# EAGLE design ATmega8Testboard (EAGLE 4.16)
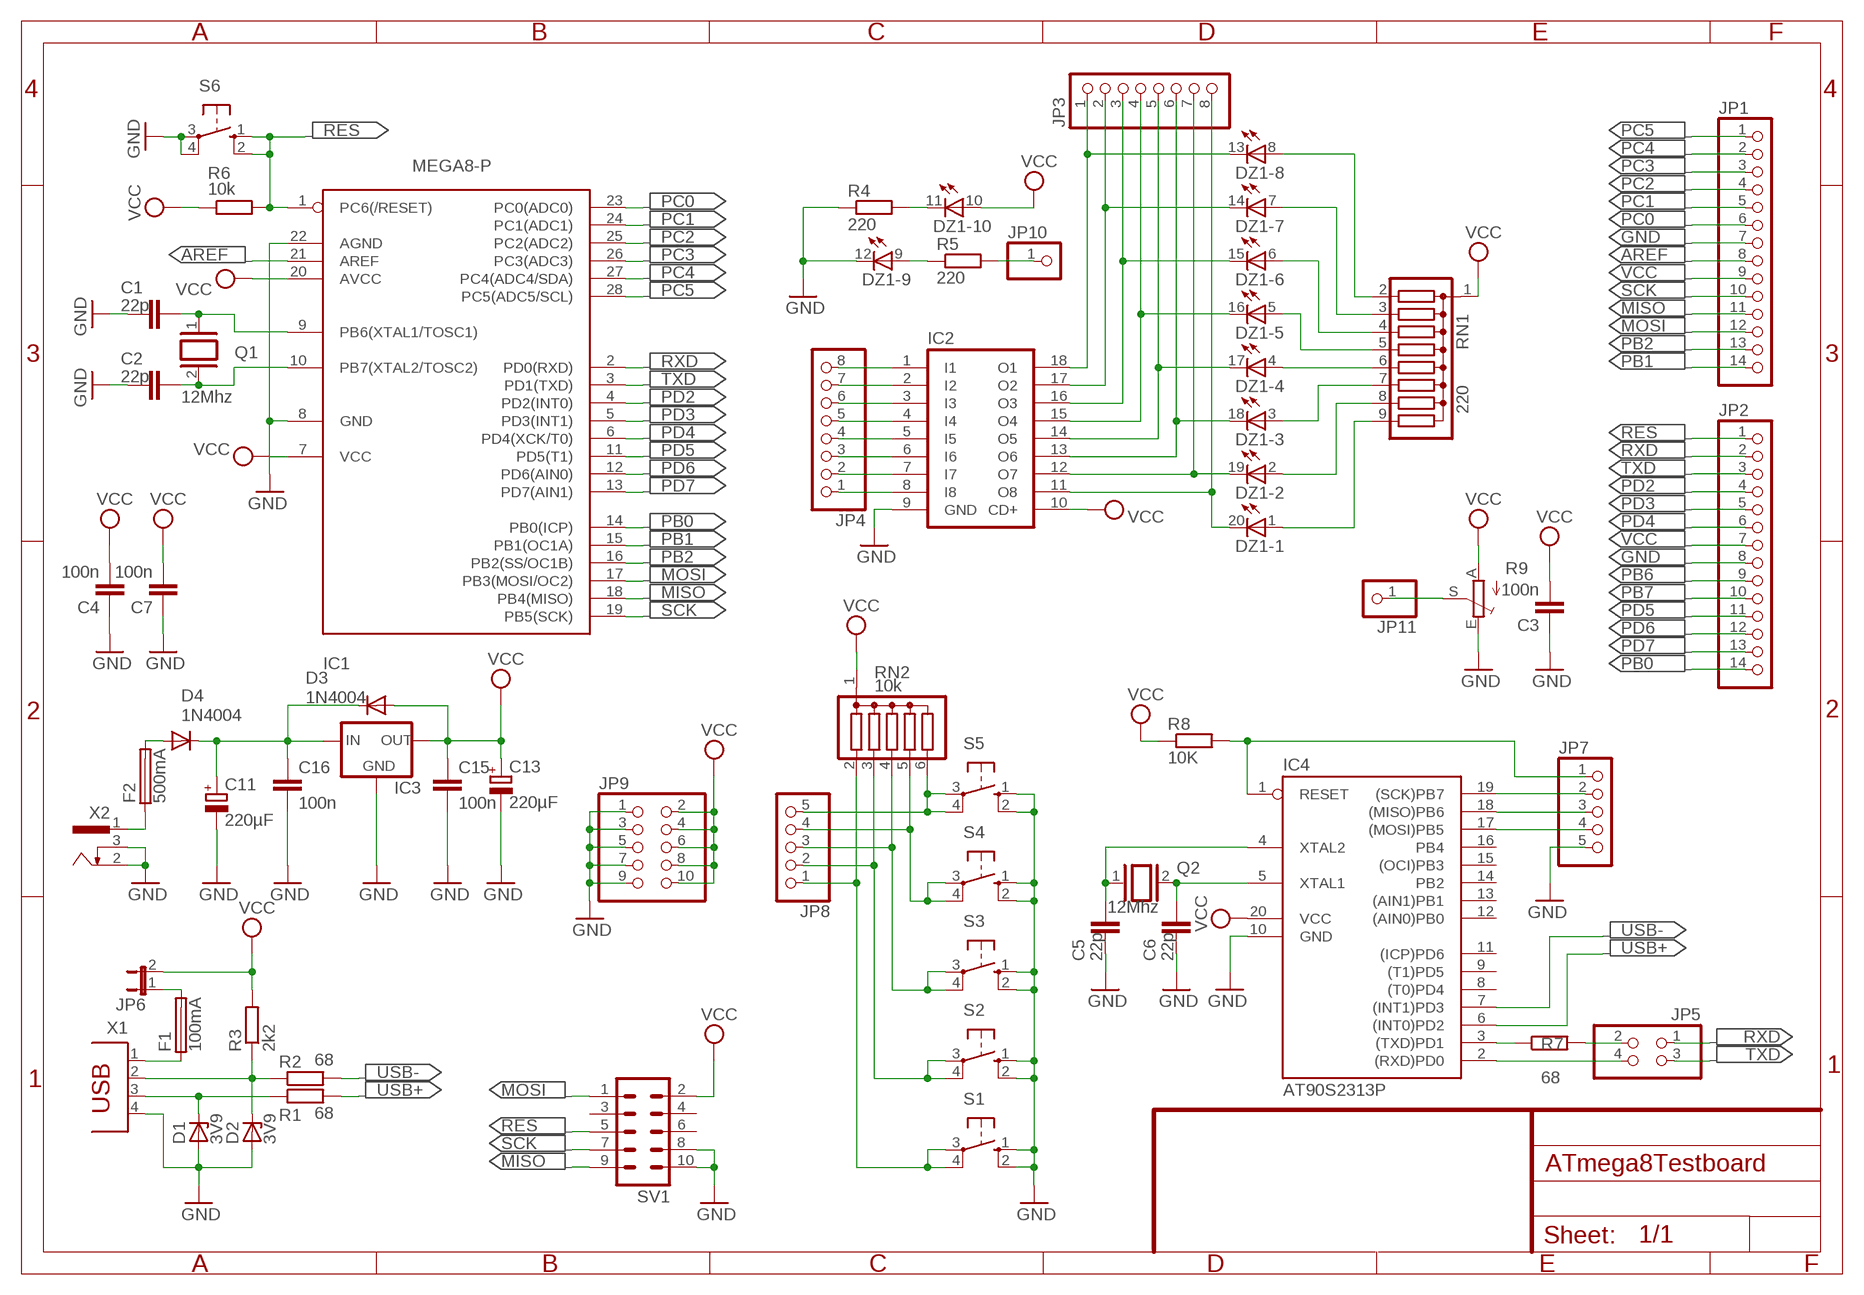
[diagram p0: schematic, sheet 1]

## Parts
C1  22p  C-EU025-024X044  [C025-024X044]
C2  22p  C-EU025-024X044  [C025-024X044]
C3  100n  C-EU025-024X044  [C025-024X044]
C4  100n  C-EU025-024X044  [C025-024X044]
C5  22p  C-EU025-024X044  [C025-024X044]
C6  22p  C-EU025-024X044  [C025-024X044]
C7  100n  C-EU025-024X044  [C025-024X044]
C11  220µF  CPOL-EUE3.5-8  [E3,5-8]
C13  220µF  CPOL-EUE3.5-8  [E3,5-8]
C15  100n  C-EU050-024X044  [C050-024X044]
C16  100n  C-EU050-024X044  [C050-024X044]
D1  3V9  BZX55  [DO35Z10]
D2  3V9  BZX55  [DO35Z10]
D3  1N4004  [DO41-10]
D4  1N4004  [DO41-10]
DZ1  LB10  [LB10]
F1  100mA  PICOFUSE  [PICOFUSE]
F2  500mA  PICOFUSE  [PICOFUSE]
IC1  MEGA8-P  [DIL28-3]
IC2  ULN2803A  [DIL18]
IC3  78XXL  [78XXL]
IC4  AT90S2313P  [DIL20]
JP1  PINHD-1X14  [1X14]
JP2  PINHD-1X14  [1X14]
JP3  PINHD-1X8  [1X08]
JP4  PINHD-1X8  [1X08]
JP5  PINHD-2X2  [2X02]
JP6  JP1E  [JP1]
JP7  PINHD-1X5  [1X05]
JP8  PINHD-1X5  [1X05]
JP9  PINHD-2X5  [2X05]
JP10  PINHD-1X1  [1X01]
JP11  PINHD-1X1  [1X01]
Q1  12Mhz  XTAL/S  [QS]
Q2  12Mhz  XTAL/S  [QS]
R1  68  R-EU_0207/10  [0207/10]
R2  68  R-EU_0207/10  [0207/10]
R3  2k2  R-EU_0207/10  [0207/10]
R4  220  R-EU_0207/10  [0207/10]
R5  220  R-EU_0207/10  [0207/10]
R6  10k  R-EU_0207/10  [0207/10]
R7  68  R-EU_0207/10  [0207/10]
R8  10K  R-EU_0207/10  [0207/10]
R9  TRIM_EU-LI15  [LI15]
RN1  220  G08R  [SIL9]
RN2  10k  G05R  [SIL6]
S1  10-XX  [B3F-10XX]
S2  10-XX  [B3F-10XX]
S3  10-XX  [B3F-10XX]
S4  10-XX  [B3F-10XX]
S5  10-XX  [B3F-10XX]
S6  10-XX  [B3F-10XX]
SV1  ML10  [ML10]
X1  PN61729  [PN61729]
X2  SCD-014A  [SCD-014-A]

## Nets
/RXD: JP5.2 R7.2
/TXD: IC4.2((RXD)PD0) JP5.4
AREF: IC1.21(AREF) JP1.8
GND: C1.1 C2.1 C3.1 C4.1 C5.1 C6.1 C7.1 C11.- C13.- C15.2 C16.2 D1.A D2.A DZ1.12(-9:C) IC1.8(GND) IC1.22(AGND) IC2.9(GND) IC3.GND IC4.10(GND) JP1.7 JP2.8 JP7.5 JP9.1 JP9.3 JP9.5 JP9.7 JP9.9 R4.1 R9.E S1.1(S) S1.2(S1) S2.1(S) S2.2(S1) S3.1(S) S3.2(S1) S4.1(S) S4.2(S1) S5.1(S) S5.2(S1) S6.3(P) S6.4(P1) SV1.8 SV1.10 X1.4 X2.2 X2.3
MISO: IC1.18(PB4(MISO)) JP1.11 SV1.9
MOSI: IC1.17(PB3(MOSI/OC2)) JP1.12 SV1.1
N$1: JP11.1 R9.S
N$3: DZ1.1(-1:A) RN1.9
N$4: DZ1.13(-8:C) IC2.18(O1) JP3.1
N$5: D1.C R1.1 X1.3
N$6: D2.C R2.1 R3.1 X1.2
N$7: DZ1.14(-7:C) IC2.17(O2) JP3.2
N$8: DZ1.15(-6:C) IC2.16(O3) JP3.3
N$9: DZ1.16(-5:C) IC2.15(O4) JP3.4
N$10: DZ1.17(-4:C) IC2.14(O5) JP3.5
N$11: DZ1.18(-3:C) IC2.13(O6) JP3.6
N$12: DZ1.19(-2:C) IC2.12(O7) JP3.7
N$13: DZ1.20(-1:C) IC2.11(O8) JP3.8
N$18: DZ1.5(-5:A) RN1.5
N$19: DZ1.4(-4:A) RN1.6
N$20: DZ1.3(-3:A) RN1.7
N$21: DZ1.2(-2:A) RN1.8
N$22: DZ1.6(-6:A) RN1.4
N$23: DZ1.7(-7:A) RN1.3
N$24: DZ1.8(-8:A) RN1.2
N$25: IC2.1(I1) JP4.8
N$26: IC2.2(I2) JP4.7
N$27: IC2.3(I3) JP4.6
N$28: IC2.4(I4) JP4.5
N$29: IC2.5(I5) JP4.4
N$30: IC2.6(I6) JP4.3
N$31: IC2.7(I7) JP4.2
N$32: IC2.8(I8) JP4.1
N$33: DZ1.11(-10:C) R4.2
N$34: DZ1.9(-9:A) R5.1
N$35: IC4.3((TXD)PD1) R7.1
N$36: C5.2 IC4.4(XTAL2) Q2.1
N$37: F1.2 JP6.1
N$38: C6.2 IC4.5(XTAL1) Q2.2
N$39: F1.1 X1.1
N$40: IC4.19((SCK)PB7) JP7.2
N$41: IC4.18((MISO)PB6) JP7.3
N$42: IC4.17((MOSI)PB5) JP7.4
N$43: JP10.1 R5.2
N$44: IC4.1(RESET) JP7.1 R8.2
N$45: D4.A F2.2
N$46: F2.1 X2.1
N$47: JP8.5 RN2.6 S5.3(P) S5.4(P1)
N$48: JP8.4 RN2.5 S4.3(P) S4.4(P1)
N$49: JP8.3 RN2.4 S3.3(P) S3.4(P1)
N$50: JP8.2 RN2.3 S2.3(P) S2.4(P1)
N$51: JP8.1 RN2.2 S1.3(P) S1.4(P1)
N$250: C11.+ C16.1 D3.C D4.C IC3.IN
PB0: IC1.14(PB0(ICP)) JP2.14
PB1: IC1.15(PB1(OC1A)) JP1.14
PB2: IC1.16(PB2(SS/OC1B)) JP1.13
PB6: C1.2 IC1.9(PB6(XTAL1/TOSC1)) JP2.9 Q1.1
PB7: C2.2 IC1.10(PB7(XTAL2/TOSC2)) JP2.10 Q1.2
PC0: IC1.23(PC0(ADC0)) JP1.6
PC1: IC1.24(PC1(ADC1)) JP1.5
PC2: IC1.25(PC2(ADC2)) JP1.4
PC3: IC1.26(PC3(ADC3)) JP1.3
PC4: IC1.27(PC4(ADC4/SDA)) JP1.2
PC5: IC1.28(PC5(ADC5/SCL)) JP1.1
PD2: IC1.4(PD2(INT0)) JP2.4
PD3: IC1.5(PD3(INT1)) JP2.5
PD4: IC1.6(PD4(XCK/T0)) JP2.6
PD5: IC1.11(PD5(T1)) JP2.11
PD6: IC1.12(PD6(AIN0)) JP2.12
PD7: IC1.13(PD7(AIN1)) JP2.13
RES: IC1.1(PC6(/RESET)) JP2.1 R6.2 S6.1(S) S6.2(S1) SV1.5
RXD: IC1.2(PD0(RXD)) JP2.2 JP5.1
SCK: IC1.19(PB5(SCK)) JP1.10 SV1.7
TXD: IC1.3(PD1(TXD)) JP2.3 JP5.3
USB+: IC4.6((INT0)PD2) R1.2
USB-: IC4.7((INT1)PD3) R2.2
VCC: C3.2 C4.2 C7.2 C13.+ C15.1 D3.A DZ1.10(-10:A) IC1.7(VCC) IC1.20(AVCC) IC2.10(CD+) IC3.OUT IC4.20(VCC) JP1.9 JP2.7 JP6.2 JP9.2 JP9.4 JP9.6 JP9.8 JP9.10 R3.2 R6.1 R8.1 R9.A RN1.1 RN2.1 SV1.2
Unconnected: IC4.8((T0)PD4) IC4.9((T1)PD5) IC4.11((ICP)PD6) IC4.12((AIN0)PB0) IC4.13((AIN1)PB1) IC4.14(PB2) IC4.15((OCI)PB3) IC4.16(PB4) SV1.3 SV1.4 SV1.6

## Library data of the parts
C1-C7 C15 C16 = rcl:C-EU: CAPACITOR, European symbol
C11 C13 = rcl:CPOL-EU: POLARIZED CAPACITOR, European symbol
D1 D2 = diode:BZX55: Z DIODE
D3 D4 = diode:1N4004: DIODE
DZ1 = led:LB10: LED BLOCK 10-LED bar graph, DIL, Siemens
F1 F2 = fuse:PICOFUSE: PICOFUSE
IC1 = avr-1:MEGA8-P: MICROCONTROLLER 8 Kbytes FLASH 1 kbytes SRAM 512 bytes EEPROM USART 4-channel 10 bit ADC 2-channel 8 bit ADC
IC2 = uln-udn:ULN2803A: DRIVER ARRAY
IC3 = v-reg:78XXL: VOLTAGE REGULATOR
IC4 = atmel:AT90S2313: MICROCONTROLLER 2 Kbytes FLASH 128 bytes SRAM 128 bytes EEPROM UART
JP1 JP2 = pinhead:PINHD-1X14: PIN HEADER
JP3 JP4 = pinhead:PINHD-1X8: PIN HEADER
JP5 = pinhead:PINHD-2X2: PIN HEADER
JP6 = jumper:JP1E: JUMPER
JP7 JP8 = pinhead:PINHD-1X5: PIN HEADER
JP9 = pinhead:PINHD-2X5: PIN HEADER
JP10 JP11 = pinhead:PINHD-1X1: PIN HEADER
Q1 Q2 = special:XTAL/S: CRYSTAL
R1-R8 = rcl:R-EU_: RESISTOR, European symbol
R9 = pot:TRIM_EU-: POTENTIOMETER
RN1 = resistor-sil:G08R: SIL RESISTOR
RN2 = resistor-sil:G05R: SIL RESISTOR
S1-S6 = switch-omron:10-XX: OMRON SWITCH
SV1 = con-harting-ml:ML10: HARTING
X1 = con-berg:PN61729: BERG USB connector
X2 = con-shiua-chyuan:SCD-014A: Power Jack 2.5mm

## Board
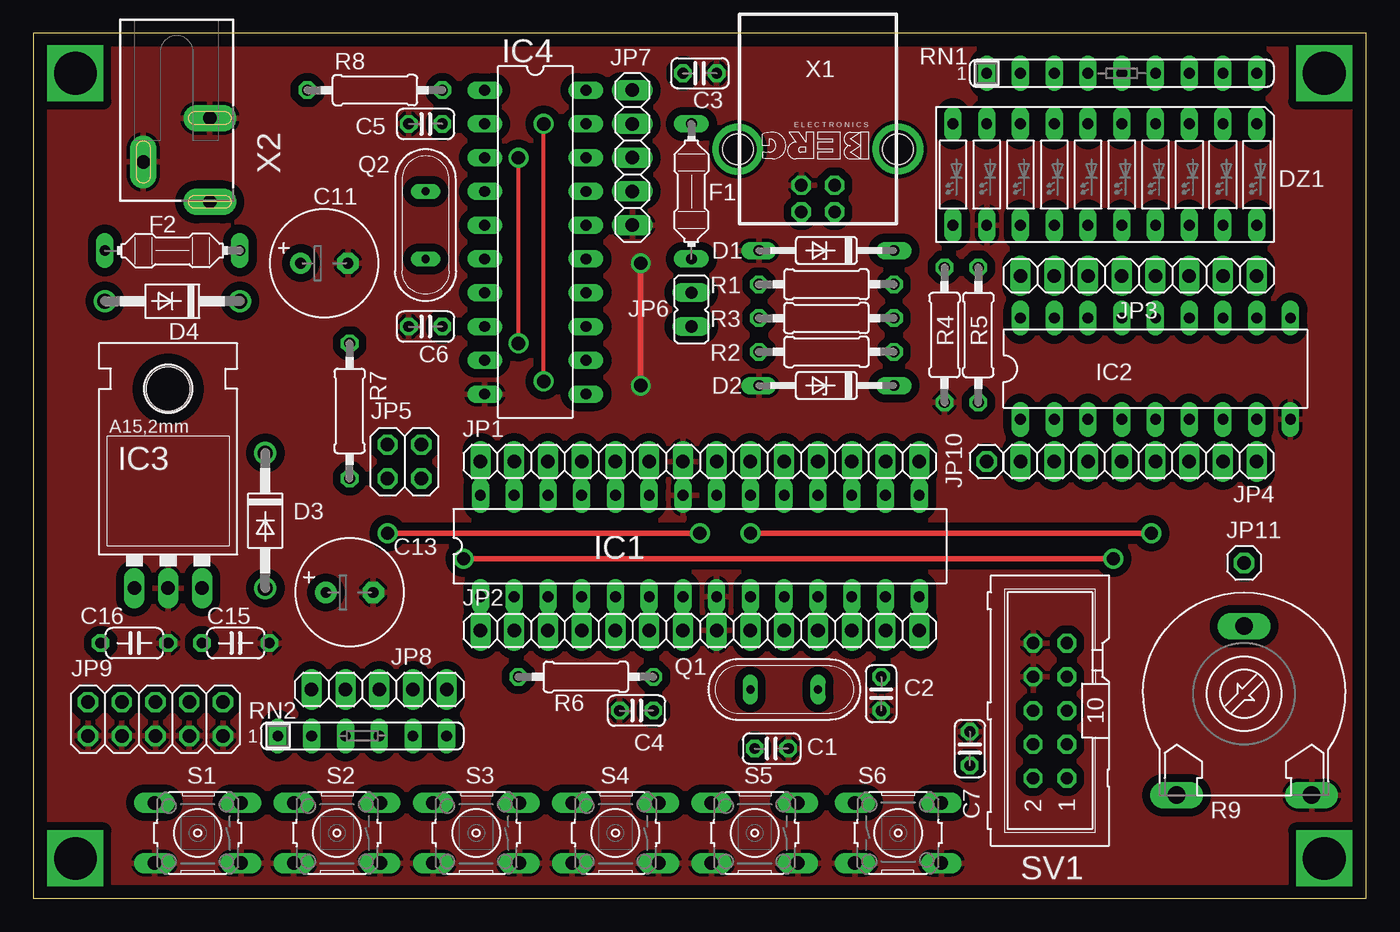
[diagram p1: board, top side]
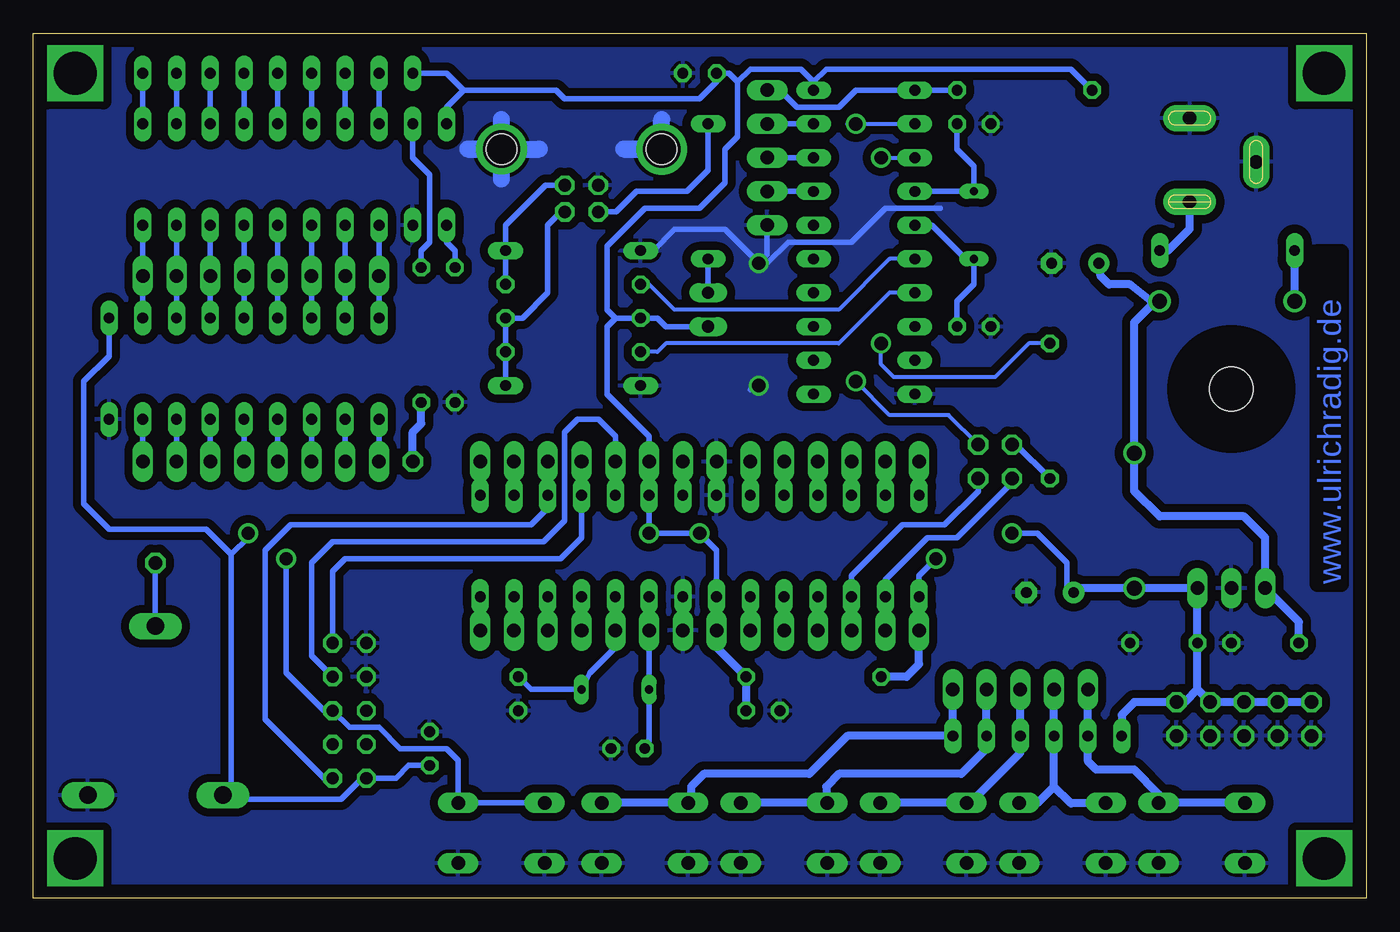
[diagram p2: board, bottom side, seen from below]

Size 100.31 x 65.07 mm. Coordinates in mm from the lower left corner, seen from the top.
Outline: 0,0 100.31,0 100.31,65.07 0,65.07 0,0
Copper layers (1*16): Top 0.035mm / dielectric 1.5mm / Bottom 0.035mm
Design rules "default": minimum track width 10mil, minimum drill 24mil, track to track 8mil, track to pad 8mil, pad to pad 8mil, via to via 8mil, smd to smd 8mil, copper to edge 40mil, drill to drill 8mil, minimum pad ring 10mil, minimum via ring 8mil, stop-mask expansion 4mil, vias tented up to drill 0mil, thermal gap 10mil

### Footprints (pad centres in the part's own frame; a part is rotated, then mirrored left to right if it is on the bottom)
C025-024X044 = drill 0.813 octagon: 1 -1.27,0; 2 1.27,0
E3,5-8 = drill 0.813 pad 1.6 round: + -1.778,0 | drill 0.813 pad 1.6 octagon: - 1.778,0
C050-024X044 = drill 0.813 octagon: 1 -2.54,0; 2 2.54,0
DO35Z10 = drill 0.813 long: A 5.08,0; C -5.08,0
DO41-10 = drill 1.118 round: A 5.08,0; C -5.08,0
LB10 = drill 0.813 long: 1 -11.43,-3.81; 2 -8.89,-3.81; 3 -6.35,-3.81; 4 -3.81,-3.81; 5 -1.27,-3.81; 6 1.27,-3.81; 7 3.81,-3.81; 8 6.35,-3.81; 9 8.89,-3.81; 10 11.43,-3.81; 11 11.43,3.81; 12 8.89,3.81; 13 6.35,3.81; 14 3.81,3.81; 15 1.27,3.81; 16 -1.27,3.81; 17 -3.81,3.81; 18 -6.35,3.81; 19 -8.89,3.81; 20 -11.43,3.81
PICOFUSE = drill 0.813 long: 1 -5.08,0; 2 5.08,0
DIL28-3 = drill 0.813 long: 1 -16.51,-3.81; 2 -13.97,-3.81; 3 -11.43,-3.81; 4 -8.89,-3.81; 5 -6.35,-3.81; 6 -3.81,-3.81; 7 -1.27,-3.81; 8 1.27,-3.81; 9 3.81,-3.81; 10 6.35,-3.81; 11 8.89,-3.81; 12 11.43,-3.81; 13 13.97,-3.81; 14 16.51,-3.81; 15 16.51,3.81; 16 13.97,3.81; 17 11.43,3.81; 18 8.89,3.81; 19 6.35,3.81; 20 3.81,3.81; 21 1.27,3.81; 22 -1.27,3.81; 23 -3.81,3.81; 24 -6.35,3.81; 25 -8.89,3.81; 26 -11.43,3.81; 27 -13.97,3.81; 28 -16.51,3.81
DIL18 = drill 0.813 long: 1 -10.16,-3.81; 2 -7.62,-3.81; 3 -5.08,-3.81; 4 -2.54,-3.81; 5 0,-3.81; 6 2.54,-3.81; 7 5.08,-3.81; 8 7.62,-3.81; 9 10.16,-3.81; 10 10.16,3.81; 11 7.62,3.81; 12 5.08,3.81; 13 2.54,3.81; 14 0,3.81; 15 -2.54,3.81; 16 -5.08,3.81; 17 -7.62,3.81; 18 -10.16,3.81
78XXL = drill 1.016 long: GND 0,-3.81; IN -2.54,-3.81; OUT 2.54,-3.81 | hole 3.302: 0,11.176
DIL20 = drill 0.813 long: 1 -11.43,-3.81; 2 -8.89,-3.81; 3 -6.35,-3.81; 4 -3.81,-3.81; 5 -1.27,-3.81; 6 1.27,-3.81; 7 3.81,-3.81; 8 6.35,-3.81; 9 8.89,-3.81; 10 11.43,-3.81; 11 11.43,3.81; 12 8.89,3.81; 13 6.35,3.81; 14 3.81,3.81; 15 1.27,3.81; 16 -1.27,3.81; 17 -3.81,3.81; 18 -6.35,3.81; 19 -8.89,3.81; 20 -11.43,3.81
1X14 = drill 1.016 long: 1 -16.51,0; 2 -13.97,0; 3 -11.43,0; 4 -8.89,0; 5 -6.35,0; 6 -3.81,0; 7 -1.27,0; 8 1.27,0; 9 3.81,0; 10 6.35,0; 11 8.89,0; 12 11.43,0; 13 13.97,0; 14 16.51,0
1X08 = drill 1.016 long: 1 -8.89,0; 2 -6.35,0; 3 -3.81,0; 4 -1.27,0; 5 1.27,0; 6 3.81,0; 7 6.35,0; 8 8.89,0
2X02 = drill 1.016 octagon: 1 -1.27,-1.27; 2 -1.27,1.27; 3 1.27,-1.27; 4 1.27,1.27
JP1 = drill 0.914 long: 1 0,-1.27; 2 0,1.27
1X05 = drill 1.016 long: 1 -5.08,0; 2 -2.54,0; 3 0,0; 4 2.54,0; 5 5.08,0
2X05 = drill 1.016 octagon: 1 -5.08,-1.27; 2 -5.08,1.27; 3 -2.54,-1.27; 4 -2.54,1.27; 5 0,-1.27; 6 0,1.27; 7 2.54,-1.27; 8 2.54,1.27; 9 5.08,-1.27; 10 5.08,1.27
1X01 = drill 1.016 octagon: 1 0,0
QS = drill 0.61 long: 1 -2.54,0; 2 2.54,0
0207/10 = drill 0.813 octagon: 1 -5.08,0; 2 5.08,0
LI15 = drill 1.321 long: A -5.08,-7.62; E 5.08,-7.62; S 0,5.08
SIL9 = drill 0.813 long: 1 -10.16,0; 2 -7.62,0; 3 -5.08,0; 4 -2.54,0; 5 0,0; 6 2.54,0; 7 5.08,0; 8 7.62,0; 9 10.16,0
SIL6 = drill 0.813 long: 1 -6.35,0; 2 -3.81,0; 3 -1.27,0; 4 1.27,0; 5 3.81,0; 6 6.35,0
B3F-10XX = drill 1.016 long: 1 -3.251,2.261; 2 3.251,2.261; 3 -3.251,-2.261; 4 3.251,-2.261
ML10 = drill 0.914 octagon: 1 -5.08,-1.27; 2 -5.08,1.27; 3 -2.54,-1.27; 4 -2.54,1.27; 5 0,-1.27; 6 0,1.27; 7 2.54,-1.27; 8 2.54,1.27; 9 5.08,-1.27; 10 5.08,1.27
PN61729 = drill 0.95 octagon: 1 1.25,4.71; 2 -1.25,4.71; 3 -1.25,2.71; 4 1.25,2.71 | hole 2.3: -6.02,0; 6.02,0
SCD-014-A = drill 1 pad 2 long: 1 -2.5,13.8; 2 -2.5,7.5; 3 2.5,10.8

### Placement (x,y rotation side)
C1  55.56,11.27 180 top
C2  63.81,15.39 90 top
C3  50.16,62.06 180 top
C4  45.4,14.12 0 top
C5  29.52,58.26 0 top
C6  29.52,43.02 0 top
C7  70.48,11.27 270 top
C11  21.9,47.78 0 top
C13  23.81,23.01 0 top
C15  15.23,19.2 0 top
C16  7.62,19.2 0 top
D1  59.68,48.73 180 top
D2  59.68,38.57 180 top
D3  17.46,28.41 270 top
D4  10.47,44.92 180 top
DZ1  80.64,54.45 180 top
F1  49.52,53.18 270 top
F2  10.47,48.73 180 top
IC1  50.16,26.51 0 top
IC2  84.45,39.84 0 top
IC3  10.15,27.14 0 top
IC4  37.78,49.37 270 top
JP1  50.16,32.86 0 top
JP2  50.16,20.16 0 top
JP3  83.18,46.83 0 top
JP4  83.18,32.86 180 top
JP5  27.94,32.86 0 top
JP6  49.52,44.29 180 top
JP7  45.08,55.72 270 top
JP8  26.03,15.71 0 top
JP9  9.2,13.49 0 top
JP10  71.75,32.86 0 top
JP11  91.12,25.23 0 top
Q1  56.51,15.71 0 top
Q2  29.52,50.63 270 top
R1  59.68,46.19 180 top
R2  59.68,41.11 180 top
R3  59.68,43.65 180 top
R4  68.58,42.38 90 top
R5  71.12,42.38 270 top
R6  41.59,16.66 180 top
R7  23.81,36.66 270 top
R8  25.71,60.8 0 top
R9  91.12,15.39 0 top
RN1  81.91,62.06 0 top
RN2  24.76,12.22 0 top
S1  12.38,4.92 180 top
S2  22.86,4.92 180 top
S3  33.33,4.92 180 top
S4  43.81,4.92 180 top
S5  54.29,4.92 180 top
S6  65.08,4.92 0 top
SV1  76.51,14.12 90 top
X1  59.05,56.35 180 top
X2  10.79,66.19 180 top

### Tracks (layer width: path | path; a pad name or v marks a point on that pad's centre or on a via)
/RXD
  Bottom 0.406: JP5.2 26.35,34.12 R7.2
/TXD  (via drill 1)
  Top 0.305: v38.41,38.89 v38.41,58.26
  Bottom 0.305: IC4.2 v38.41,58.26 39.05,58.26 | v38.41,38.89 35.87,36.35 31.43,36.35 JP5.4
AREF
  Bottom 0.406: IC1.21 JP1.8
GND  (via drill 1, 2.8)
  Top 0.406: v45.71,47.78 v45.71,38.57
  Bottom 0.406: IC1.22 JP1.7 | JP2.8 IC1.8 | JP7.5 45.08,48.41 v45.71,47.78 | v45.71,38.57 46.03,38.57 46.35,38.25 | D1.A 53.65,48.73 52.06,50.32 48.25,50.32 v45.71,47.78 | v45.71,47.78 45.08,47.78 43.49,49.37 38.73,49.37 36.19,51.91 32.06,51.91
  Bottom 1.27: v53.01,56.35 55.88,56.35 53.02,56.35 53.02,58.57 | 62.22,56.35 62.22,56.36 v65.07,56.36 67.62,56.36 67.62,56.35 65.08,56.35 | 65.08,54.13 65.08,56.35 | 65.08,56.35 65.08,58.57
  pour Bottom (isolate 0.61): -0.01,64.92 100.33,64.92 100.33,-0.17 -0.01,-0.17
  pour Top (isolate 0.61): -0.01,64.92 100.33,64.92 100.33,0.15 -0.01,0.15 -0.01,64.6
MISO
  Bottom 0.406: JP1.11 IC1.18 59.05,27.14 60.64,25.55 76.83,25.55 77.78,24.6 SV1.9
MOSI
  Bottom 0.406: JP1.12 IC1.17 61.59,29.36 62.86,28.09 80.96,28.09 82.86,26.19 82.86,13.49 78.42,9.04 SV1.1
N$1
  Bottom 0.406: 91.12,25.55 JP11.1 R9.S
N$3
  Bottom 0.406: DZ1.1 RN1.9
N$4
  Bottom 0.406: DZ1.13 JP3.1 IC2.18
N$5
  Bottom 0.406: X1.3 61.76,53.64 64.77,50.63 D1.C R1.1
N$6
  Bottom 0.406: X1.2 60.59,51.64 61.59,50.63 61.59,45.55 63.49,43.65 R3.1 R2.1 D2.C
N$7
  Bottom 0.406: DZ1.14 JP3.2 IC2.17
N$8
  Bottom 0.406: DZ1.15 JP3.3 IC2.16
N$9
  Bottom 0.406: DZ1.16 JP3.4 IC2.15
N$10
  Bottom 0.406: DZ1.17 JP3.5 IC2.14
N$11
  Bottom 0.406: DZ1.18 JP3.6 IC2.13
N$12
  Bottom 0.406: DZ1.19 JP3.7 IC2.12
N$13
  Bottom 0.406: DZ1.20 JP3.8 IC2.11
N$14  (via drill 3.2)
  other vias: 3.17,62.06
N$15  (via drill 3.2)
  other vias: 3.17,3.01
N$16  (via drill 3.2)
  other vias: 97.15,3.01
N$17  (via drill 3.2)
  other vias: 97.15,62.06
N$18
  Bottom 0.406: DZ1.5 RN1.5
N$19
  Bottom 0.406: DZ1.4 RN1.6
N$20
  Bottom 0.406: DZ1.3 RN1.7
N$21
  Bottom 0.406: DZ1.2 RN1.8
N$22
  Bottom 0.406: DZ1.6 RN1.4
N$23
  Bottom 0.406: DZ1.7 RN1.3
N$24
  Bottom 0.406: DZ1.8 RN1.2
N$25
  Bottom 0.406: JP4.8 IC2.1
N$26
  Bottom 0.406: JP4.7 IC2.2
N$27
  Bottom 0.406: JP4.6 IC2.3
N$28
  Bottom 0.406: JP4.5 IC2.4
N$29
  Bottom 0.406: JP4.4 IC2.5
N$30
  Bottom 0.406: JP4.3 IC2.6
N$31
  Bottom 0.406: JP4.2 IC2.7
N$32
  Bottom 0.406: JP4.1 IC2.8
N$33
  Bottom 0.406: R4.2 68.58,48.73 69.21,49.37 DZ1.11
N$34
  Bottom 0.406: R5.1 71.12,48.73 70.48,49.37 70.48,54.45 71.75,55.72 DZ1.9
N$35  (via drill 1)
  Top 0.305: v36.51,41.74 v36.51,55.72
  Bottom 0.305: v36.51,55.72 IC4.3 | R7.1 25.39,41.74 27.94,39.2 35.55,39.2 36.51,40.16 v36.51,41.74
N$36
  Bottom 0.406: IC4.4 Q2.1 29.52,55.08 30.79,56.35 C5.2
N$37
  Bottom 0.406: JP6.1 F1.2
N$38
  Bottom 0.406: IC4.5 32.7,50.63 30.16,48.09 Q2.2 29.52,46.19 30.79,44.92 C6.2
N$39
  Bottom 0.406: F1.1 49.52,54.76 51.11,53.18 54.92,53.18 56.46,51.64 X1.1
N$40
  Bottom 0.406: IC4.19 JP7.2
N$41
  Bottom 0.406: IC4.18 JP7.3
N$42
  Bottom 0.406: IC4.17 JP7.4
N$43
  Bottom 0.61: R5.2 71.12,35.71 71.75,35.08 71.75,33.17 72.07,32.86 JP10.1
N$44
  Bottom 0.406: JP7.1 44.13,60.8 42.86,59.52 39.68,59.52 38.41,60.8 IC4.1 R8.2
N$45
  Bottom 0.406: D4.A 5.08,44.92 5.39,45.24
  Bottom 0.61: 5.39,45.24 F2.2
N$46
  Bottom 0.406: 14.92,48.73 F2.1
  Bottom 0.61: X2.1 13.29,50.36 14.92,48.73
N$47
  Bottom 0.61: S5.3 57.5,7.18 57.46,7.14 57.42,7.18 S5.4 51.04,7.38 51.11,7.46 50.79,7.77 50.79,8.41 49.84,9.36 41.9,9.36 39.05,12.22 RN2.6 JP8.5
N$48
  Bottom 0.61: S4.3 40.99,7.18 40.95,7.14 40.91,7.18 S4.4 40.56,7.38 40.63,7.46 40.63,8.41 39.68,9.36 30.48,9.36 28.57,11.27 RN2.5 JP8.4
N$49
  Bottom 0.61: S3.3 30.2,7.18 30.16,7.14 30.12,7.18 S3.4 29.8,7.18 26.03,10.95 RN2.4 26.03,15.39 26.35,15.71 JP8.3
N$50
  Bottom 0.61: S2.3 26.07,7.18 26.03,7.14 25.99,7.18 24.72,7.18 23.49,8.41 | 23.49,8.41 RN2.3 JP8.2 | 23.49,8.41 22.22,7.14 19.68,7.14 19.64,7.18 S2.4
N$51
  Bottom 0.61: S1.4 15.51,7.18 15.55,7.14 15.59,7.18 S1.3 15.63,7.85 17.46,9.68 20.32,9.68 20.95,10.31 RN2.2 JP8.1
N$250
  Bottom 0.406: 20,47.78 C11.+
  Bottom 0.61: 16.19,44.92 D4.C | 16.19,44.92 17.78,46.19 19.36,46.19 20,46.83 20,47.78 | C16.1 5.08,20.79 IC3.IN 7.62,27.14 9.2,28.73 15.55,28.73 17.46,30.63 D3.C 17.46,43.33 16.19,44.6 16.19,44.92
PB0
  Bottom 0.406: JP2.14 IC1.14
PB1
  Bottom 0.406: IC1.15 JP1.14
PB2
  Bottom 0.406: IC1.16 JP1.13
PB6
  Bottom 0.406: C1.2 53.97,11.58 Q1.1 JP2.9 IC1.9
PB7
  Bottom 0.406: C2.2 62.86,15.71 Q1.2 58.41,16.98 56.51,18.89 JP2.10 IC1.10
PC0
  Bottom 0.406: IC1.23 JP1.6
PC1
  Bottom 0.406: IC1.24 JP1.5
PC2
  Bottom 0.406: IC1.25 JP1.4
PC3
  Bottom 0.406: IC1.26 JP1.3
PC4
  Bottom 0.406: IC1.27 JP1.2
PC5
  Bottom 0.406: IC1.28 JP1.1
PD2
  Bottom 0.406: JP2.4 IC1.4
PD3
  Bottom 0.406: JP2.5 IC1.5
PD4
  Bottom 0.406: JP2.6 IC1.6
PD5
  Bottom 0.406: JP2.11 IC1.11
PD6
  Bottom 0.406: JP2.12 IC1.12
PD7
  Bottom 0.406: JP2.13 IC1.13
RES  (via drill 1)
  Top 0.406: v32.38,25.55 v81.28,25.55
  Bottom 0.406: IC1.1 JP2.1 IC1.1 | IC1.1 33.65,24.28 v32.38,25.55 | v81.28,25.55 81.28,16.98 78.42,14.12 SV1.5 76.51,12.85 74.29,12.85 72.7,11.27 69.21,11.27 68.33,10.39 S6.2 61.95,7.18 61.91,7.14 61.87,7.18 S6.1
  Bottom 0.61: JP2.1 33.65,17.62 34.6,16.66 R6.2
RXD
  Bottom 0.406: JP2.2 IC1.2 36.19,23.96 33.02,27.14 30.79,27.14 26.67,31.27 JP5.1
SCK
  Bottom 0.406: JP1.10 IC1.19 JP1.10 | JP1.10 56.51,34.76 57.78,36.03 59.37,36.03 60.32,35.08 60.32,28.41 61.91,26.82 77.78,26.82 79.37,25.23 79.37,18.25 SV1.7
TXD
  Bottom 0.406: JP2.3 IC1.3 38.73,24.28 34.92,28.09 31.75,28.09 29.21,30.63 JP5.3
USB+
  Bottom 0.305: R1.2 53.97,46.19 52.06,44.29 39.68,44.29 35.87,48.09 IC4.6
USB-
  Bottom 0.305: IC4.7 35.87,45.55 39.68,41.74 52.7,41.74 53.34,41.11 R2.2
VCC  (via drill 1)
  Top 0.406: v53.97,27.46 v84.13,27.46 | v26.67,27.46 v50.16,27.46
  Bottom 0.406: 67.94,60.8 60.95,60.8 60.32,60.16 50.16,60.16 48.89,61.43 C3.2 47.94,62.06 47.3,61.43 | DZ1.10 69.21,59.52 67.94,60.8 | 67.94,60.8 69.21,62.06 RN1.1 | 56.51,43.65 57.14,43.02 57.14,37.94 53.97,34.76 JP1.9 IC1.20 v53.97,27.46 v50.16,27.46 48.89,26.19 IC1.7 JP2.7 | 56.51,43.65 R3.2 53.34,43.65 52.7,43.02 JP6.2 | 56.51,43.65 57.14,44.29 57.14,49.05 54.29,51.91 50.16,51.91 48.25,53.81 48.25,56.35 47.3,57.3 47.3,61.43 | 41.59,61.43 42.54,62.38 46.35,62.38 47.3,61.43 | 41.59,61.43 IC4.20 | 41.59,61.43 40.63,62.38 22.22,62.38 R8.1 | v26.67,27.46 24.76,27.46 22.54,25.23 22.54,23.01 C13.+ | 85.4,25.87 85.4,8.41 R9.A 85.72,7.46 77.15,7.46 75.56,9.04 SV1.2 75.24,8.73 74.93,9.04 73.02,9.04 72.07,10 C7.2 | v84.13,27.46 84.13,27.14 85.4,25.87 | 85.4,25.87 87.31,27.78 94.61,27.78 96.52,29.68 96.52,38.89 94.61,40.79 IC2.10
  Bottom 0.61: IC1.7 JP2.7 48.89,18.89 R6.1 C4.2 | C13.+ 22.22,23.33 D3.A IC3.OUT C15.1 12.69,15.71 | JP9.2 JP9.4 JP9.6 11.42,14.76 11.74,15.08 JP9.8 12.69,15.71 | 12.69,15.71 13.65,14.76 JP9.10 17.46,14.76 18.41,13.81 RN2.1

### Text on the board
Bottom: www.ulrichradig.de
bStop: www.ulrichradig.de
